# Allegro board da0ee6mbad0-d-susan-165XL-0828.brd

Outline 177.3 x 87.93 mm; copper layers: TOP, IN1, GND1, IN2, SVCC2, SGND2, IN3, GND3, IN4, BOTTOM. Coordinates in mm from the lower left corner of the outline.
Outline path: 0,43.11 0,40.26 0.5,39.76 5.9,39.76 5.9,40.36 arc(6.8,41.26) 7.7,40.36 7.7,39.76 13.1,39.76 13.1,0.5 arc(13.25,0.15) 13.6,0 17.65,0 17.65,4.41 38.95,4.41 38.95,0 43.9,0 arc(44.25,0.15) 44.4,0.5 44.4,12.5 45.4,12.5 arc(46.11,12.79) 46.4,13.5 46.4,32.5 123.1,32.5 arc(123.81,32.79) 124.1,33.5 124.1,54.11 arc(124.25,54.46) 124.6,54.61 128.95,54.61 arc(129.3,54.76) 129.45,55.11 129.45,57.61 129.44,65.41 arc(129.59,65.76) 129.94,65.91 136.1,65.91 136.4,66.21 136.4,66.91 149.8,66.91 149.8,66.21 150.1,65.91 163.31,65.91 163.61,66.21 163.61,67.91 arc(163.7,68.12) 163.91,68.21 164.91,68.21 arc(165.12,68.12) 165.21,67.91 165.21,66.21 165.51,65.91 172.32,65.91 172.32,67.08 arc(173.32,68.08) 174.32,67.08 174.32,65.91 175.3,65.91 arc(175.65,66.06) 175.8,66.41 175.8,82.93 177,82.93 177.3,83.23 177.3,84.13 177,84.43 175.8,84.43 175.8,85.43 177,85.43 177.3,85.73 177.3,86.63 177,86.93 164.62,86.93 164.32,86.63 164.32,85.43 157.52,85.43 157.52,86.63 157.22,86.93 127.83,86.93 127.53,86.63 127.53,85.43 121.73,85.43 121.73,87.33 121.53,87.53 119.93,87.53 119.73,87.33 119.73,86.93 107.77,86.93 107.77,87.33 107.57,87.53 105.97,87.53 105.77,87.33 105.77,86.93 92.28,86.93 91.98,86.63 91.98,85.43 85.18,85.43 85.18,86.63 84.88,86.93 78.8,86.93 78.8,87.63 78.5,87.93 70.9,87.93 70.6,87.63 70.6,86.93 68.7,86.93 68.4,86.63 68.4,86.43 65.8,86.43 65.8,86.63 65.5,86.93 64.05,86.93 63.75,86.63 63.75,85.81 arc(63.3,85.36) 62.85,85.81 62.85,86.63 62.55,86.93 57.43,86.93 57.13,86.63 57.13,85.86 53.1,85.86 53.1,85.16 19.71,85.16 19.71,86.63 19.41,86.93 9.8,86.93 arc(9.09,86.64) 8.8,85.93 8.8,85.31 arc(8.7,85.01) 8.43,84.83 arc(5.17,83.14) 2.86,80.3 arc(1.77,77.95) 0.89,75.53 0.89,75.16 0.78,75.16 arc(0.74,75.03) 0.7,74.9 0.7,70.98 1.2,70.49 1.2,60.49 11.5,60.49 11.5,50.51 1.22,50.51 arc(0.87,50.36) 0.72,50.01 0.72,43.61 0.5,43.61 0,43.11 ; 11.8,78.46 arc(12.09,79.17) 12.8,79.46 14.81,79.46 arc(15,79.38) 15.1,79.2 arc(15.27,78.88) 15.6,78.76 19,78.76 arc(19.33,78.88) 19.5,79.2 arc(19.6,79.38) 19.79,79.46 21.8,79.46 arc(22.51,79.17) 22.8,78.46 22.8,76.26 arc(22.71,76.05) 22.5,75.96 22.3,75.96 arc(21.95,75.81) 21.8,75.46 21.8,74.43 arc(21.85,73.97) 22.01,73.54 22.8,71.96 22.8,67.41 arc(22.51,66.7) 21.8,66.41 12.8,66.41 arc(12.09,66.7) 11.8,67.41 11.8,71.96 12.59,73.54 arc(12.75,73.97) 12.8,74.43 12.8,75.46 arc(12.65,75.81) 12.3,75.96 12.1,75.96 arc(11.89,76.05) 11.8,76.26 11.8,78.46

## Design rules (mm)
constraint set DEFAULT: min track width 0.114
net group DFP-S3(3: nets M_1_DQSN3 M_1_DQSP3
net group DFP-S3(4)W3(2.75)-T23: nets USB_P0_DN USB_P0_DP
net group DFP-S3(3)W4(3.25)-2B: nets M_0_CLKN0 M_0_CLKN2 M_0_CLKP0 M_0_CLKP2 M_1_CLKN0 M_1_CLKN2 M_1_CLKP0 M_1_CLKP2
net group DFP-S3(4)W3(2.75)-23B: nets CAM1_CSI_A_D0N CAM1_CSI_A_D0P CAM1_CSI_A_D1N CAM1_CSI_A_D1P CAM1_CSI_CLKN CAM1_CSI_CLKP CAM2_CSI_CLKN CAM2_CSI_CLKP CAM2_CSI_D0N CAM2_CSI_D0P DDI0_TX0_DN DDI0_TX0_DP DDI0_TX2_DN DDI0_TX2_DP DDI0_TX3_DN DDI0_TX3_DP MCSI_1_CLK_DN MCSI_1_CLK_DP MCSI_1_DATA0_DN MCSI_1_DATA0_DP MCSI_1_DATA1_DN MCSI_1_DATA1_DP MCSI_2_CLK_DN MCSI_2_CLK_DP MCSI_2_DATA_DN MCSI_2_DATA_DP MDSI_A0_DN MDSI_A0_DP MDSI_A1_DN MDSI_A1_DP MDSI_A2_DN MDSI_A2_DP MDSI_A3_DN MDSI_A3_DP MDSI_A_CLKN MDSI_A_CLKP USB_3G_DN USB_3G_DP
net group DFP-S3(4)W3(2.75)-T23B: nets CHG_USBDN CHG_USBDP HDMI_TXCN_R HDMI_TXCP_R HDMI_TXD0N_R HDMI_TXD0P_R HDMI_TXD1N_R HDMI_TXD1P_R HDMI_TXD2N_R HDMI_TXD2P_R N42488414 N42488420 USB2_DEBUG_DN USB2_DEBUG_DP
net group DFP-S4.5W4.5(2.5)-1234B: nets I2C_2MP_CAM_SCL I2C_2MP_CAM_SDA I2C_4_SCL I2C_4_SDA I2C_5_SCL I2C_5_SDA I2C_5MP_CAM_SCL I2C_5MP_CAM_SDA I2C_CODEC_SCL I2C_CODEC_SDA I2C_GYRO_SCL I2C_GYRO_SDA I2C_PMIC_SCL I2C_PMIC_SDA I2C_SENSOR_SCL I2C_SENSOR_SDA I2C_SENSORHUB_SCL I2C_SENSORHUB_SDA
net group DFP-S4.5W4.5(2.5)-T1234B: nets BAT_CLK BAT_DATA GPS_UART_RXD_R GPS_UART_TXD_R I2C_0_SCL I2C_0_SDA UART_BT_CTS UART_BT_RTS UART_BT_RXD UART_BT_TXD UART_GPS_RXD UART_GPS_TXD
net group W4.5(2.5)-2B: nets M_0_CKE0 M_0_CKE1 M_0_CKE2 M_0_CKE3 M_0_ODT0 M_0_ODT2 M_1_CKE0 M_1_CKE1 M_1_CKE2 M_1_CKE3 M_1_ODT0 M_1_ODT2
net group W4.5(2.5)-34B: nets M_0_DM0 M_0_DM1 M_0_DM2 M_0_DM3 M_0_DM4 M_0_DM5 M_0_DM6 M_0_DM7 M_0_DQ0 M_0_DQ1 M_0_DQ2 M_0_DQ3 M_0_DQ4 M_0_DQ5 M_0_DQ6 M_0_DQ7 M_0_DQ8 M_0_DQ9 M_0_DQ10 M_0_DQ11 M_0_DQ12 M_0_DQ13 M_0_DQ14 M_0_DQ15 M_0_DQ16 M_0_DQ17 M_0_DQ18 M_0_DQ19 M_0_DQ20 M_0_DQ21 M_0_DQ22 M_0_DQ23 M_0_DQ24 M_0_DQ25 M_0_DQ26 M_0_DQ27 M_0_DQ28 M_0_DQ29 M_0_DQ30 M_0_DQ31 M_0_DQ32 M_0_DQ33 M_0_DQ34 M_0_DQ35 M_0_DQ36 M_0_DQ37 M_0_DQ38 M_0_DQ39 M_0_DQ40 M_0_DQ41 M_0_DQ42 M_0_DQ43 M_0_DQ44 M_0_DQ45 M_0_DQ46 M_0_DQ47 M_0_DQ48 M_0_DQ49 M_0_DQ50 M_0_DQ51 M_0_DQ52 M_0_DQ53 M_0_DQ54 M_0_DQ55 M_0_DQ56 M_0_DQ57 M_0_DQ58 M_0_DQ59 M_0_DQ60 M_0_DQ61 M_0_DQ62 M_0_DQ63 M_1_DM0 M_1_DM1 M_1_DM2 M_1_DM3 M_1_DM4 M_1_DM5 M_1_DM6 M_1_DM7 M_1_DQ0 M_1_DQ1 M_1_DQ2 M_1_DQ3 M_1_DQ4 M_1_DQ5 M_1_DQ6 M_1_DQ7 M_1_DQ8 M_1_DQ9 M_1_DQ10 M_1_DQ11 M_1_DQ12 M_1_DQ13 M_1_DQ14 M_1_DQ15 M_1_DQ16 M_1_DQ17 M_1_DQ18 M_1_DQ19 M_1_DQ20 M_1_DQ21 M_1_DQ22 M_1_DQ23 M_1_DQ24 M_1_DQ25 M_1_DQ26 M_1_DQ27 M_1_DQ28 M_1_DQ29 M_1_DQ30 M_1_DQ31 M_1_DQ32 M_1_DQ33 M_1_DQ34 M_1_DQ35 M_1_DQ36 M_1_DQ37 M_1_DQ38 M_1_DQ39 M_1_DQ40 M_1_DQ41 M_1_DQ42 M_1_DQ43 M_1_DQ44 M_1_DQ45 M_1_DQ46 M_1_DQ47 M_1_DQ48 M_1_DQ49 M_1_DQ50 M_1_DQ51 M_1_DQ52 M_1_DQ53 M_1_DQ54 M_1_DQ55 M_1_DQ56 M_1_DQ57 M_1_DQ58 M_1_DQ59 M_1_DQ60 M_1_DQ61 M_1_DQ62 M_1_DQ63
net group W4.5(2.5)-1234B: nets ADCDAT BCLK BT_FM_PCM_I2S_CLK_R BT_FM_PCM_I2S_IN_R BT_FM_PCM_I2S_OUT_R BT_FM_PCM_I2S_SYNC_R DACDAT I2S_0_CLK I2S_0_FS I2S_0_RXD I2S_0_TXD I2S_1_CLK I2S_1_FS I2S_1_RXD I2S_1_TXD I2S_2_CLK I2S_2_FS I2S_2_RXD I2S_2_TXD LRCK PLT_CLK0_CAM1 PLT_CLK1_CAM2 SOC_SPI_CLK SOC_SPI_CS# SOC_SPI_MISO SOC_SPI_MOSI SUS_CLK_GPS SUS_CLK_WLAN
net group W4.5(2.5)-T123B: nets SIM_CLK SIM_DATA SIM_RST SOC_XTAL_IN SOC_XTAL_OUT STM_12M_IN STM_12M_OUT STM_12M_OUT_R USIM_DETECT
net group W4.5(2.5)-T1234: nets EMMC_CLK EMMC_CMD EMMC_DATA_0 EMMC_DATA_1 EMMC_DATA_2 EMMC_DATA_3 EMMC_DATA_4 EMMC_DATA_5 EMMC_DATA_6 EMMC_DATA_7 EMMC_RESET SDIO2_CLK SDIO2_CMD SDIO2_DATA0 SDIO2_DATA1 SDIO2_DATA2 SDIO2_DATA3 SDIO3_CD# SDIO3_CLK SDIO3_CMD SDIO3_DATA_0 SDIO3_DATA_1 SDIO3_DATA_2 SDIO3_DATA_3
net group W4.5(2.5)-T1234B: nets BT_DEV_EN CAMERA_1_RESET# CAMERA_2_RESET# CLK_USB_REF_DN CLK_USB_REF_DP CODEC_RESET# CORE_PWROK DEBUG_SVID_ALERT_B DEBUG_SVID_CLK DEBUG_SVID_DATA EMMC_RCOMP LPC_AD0 LPC_AD1 LPC_AD2 LPC_AD3 LPC_CLKOUT_1 LPC_FRAME# PLTRST# PROCHOT# RSMRST# RTC_XTAL_IN RTC_XTAL_OUT S_D_RS SENSOR_HUB_RST# SENSOR_HUB_RST_3P3_R SLP_S0IX# SLP_S3# SLP_S3#_EN SLP_S4# SOC_PWRBTN# SOC_RTEST# SOC_RTEST#_R SRT_CRST# SUS_PWRDNACK SUS_PWRDOWNACK SVID_ALERT# SVID_ALERT#_R SVID_CLK SVID_CLK_R SVID_DATA SVID_DATA_R TOUCH_RESET# USB_RCOMP
net group W4.5-T1234B: nets DDI0_RCOMP_DN DDI0_RCOMP_DP GPIO_RCOMP18 HDA_RCOMP ICLK_ICOMP ICLK_RCOMP LPC_RCOMP MCSI_COMP MDSI_COMP SDIO3_RCOMP USB_HSIC_RCOMP
net group W5-T1234B: nets DDR3_RCOMP0 DDR3_RCOMP1 DDR3_RCOMP2
net group W6(3.5: nets M_0_CA0 M_0_CA1 M_0_CA2 M_0_CA3 M_0_CA4 M_0_CA5 M_0_CA6 M_0_CA7 M_0_CA8 M_0_CA9 M_0_CS0# M_0_CS2# M_1_CA0 M_1_CA1 M_1_CA2 M_1_CA3 M_1_CA4 M_1_CA5 M_1_CA6 M_1_CA7 M_1_CA8 M_1_CA9 M_1_CS0# M_1_CS2#
net group W10-T1234B: nets +1V05 +1V8 +1V8S5 +1V24 +1V24S5 +1V24SX +1VS5 +2V8_CAM +2V85 +3.3V_PA +3V3 +3V3_NGFF +3V3PCU +3V3S5 +5V +V_VCC +V_VNN +VBL_LCM +VDDQ +VDDQ_VTT +VHDMI +VSDIO CBUCK_OUT VIN_LDO WLBT_3V3
net group W11.5-B: nets ANT_0 ANT_1 DB_ANT_B DB_ANT_C GPS_ANT GPS_EXT_LN_OUT GPS_EXT_LNA_IN GPS_RFIP GPS_SAW1_IN GPS_SAW1_OUT GPS_SAW1_OUT1 GPS_SAW2_OUT
net group W15-T3: nets HP_L1 HP_OUT_L HP_OUT_R HP_R1
net group W20-T1234B: nets CPU_VREF
net group W30-T2: nets SPK_LN SPK_LP SPK_RN SPK_RP

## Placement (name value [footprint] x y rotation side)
C1  4.7u/6.3V_4  [CC0402_S]  2.56 48.16 180 top
C2  0.1U/10V_4  [CC0402_S]  2.56 47.27 180 top
C3  0.1u/25V_4  [CC0402_S]  5.86 48.92 180 top
C4  0.1U/10V_4  [CC0402_S]  34.06 39.02 0 top
C5  1u/6.3V_4  [CC0402_S]  34.06 38.13 180 top
C6  *10P/50V_2  [CC0201_S]  34.57 37.11 180 top
C7  1u/6.3V_4  [CC0402_S]  35.71 38.51 90 top
C8  0.1U/10V_4  [CC0402_S]  36.47 34.82 90 top
C9  0.1U/10V_4  [CC0402_S]  36.6 38.51 270 top
C10  0.1U/10V_4  [CC0402_S]  37.49 38.51 270 top
C11  0.47U/6.3V_4  [CC0402_S]  39.27 76.73 90 top
C12  0.47U/6.3V_4  [CC0402_S]  39.27 74.19 270 top
C13  0.47U/6.3V_4  [CC0402_S]  39.27 69.37 90 top
C14  0.47U/6.3V_4  [CC0402_S]  39.27 59.21 90 top
C15  0.47U/6.3V_4  [CC0402_S]  39.27 55.27 90 top
C16  0.47U/6.3V_4  [CC0402_S]  39.27 52.6 270 top
C17  0.47U/6.3V_4  [CC0402_S]  41.93 74.19 90 top
C18  0.47U/6.3V_4  [CC0402_S]  41.93 55.27 270 top
C19  0.1u/10V_2  [CC0201_S]  42.44 63.53 270 top
C20  0.47uF/6.3V_2  [CC0201_S]  46.5 66.07 0 top
C21  0.47uF/6.3V_2  [CC0201_S]  48.66 63.88 270 top
C22  0.47uF/6.3V_2  [CC0201_S]  47.77 60.86 180 top
C23  0.47uF/6.3V_2  [CC0201_S]  47.85 68.73 270 top
C24  *0.1u/10V_2  [CC0201_S]  47.85 66.3 90 top
C25  *0.1u/10V_4  [CC0402_S]  48.28 75.34 90 top
C26  0.47uF/6.3V_2  [CC0201_S]  48.54 68.73 270 top
C27  0.47uF/6.3V_2  [CC0201_S]  49.25 66.68 90 top
C28  0.47uF/6.3V_2  [CC0201_S]  49.3 69.37 270 top
C29  0.47uF/6.3V_2  [CC0201_S]  49.3 61.62 90 top
C30  0.47uF/6.3V_2  [CC0201_S]  49.3 63.88 90 top
C31  0.47uF/6.3V_2  [CC0201_S]  49.98 59.51 90 top
C32  0.47uF/6.3V_2  [CC0201_S]  50.06 69.37 270 top
C33  0.47uF/6.3V_2  [CC0201_S]  50.06 61.62 90 top
C34  1U/10V_2  [CC0201_S]  51.15 68.61 180 top
C35  0.47uF/6.3V_2  [CC0201_S]  51.15 59.97 270 top
C36  0.47uF/6.3V_2  [CC0201_S]  51.36 62.97 90 top
C37  *1U/10V_2  [CC0201_S]  51.38 65.79 270 top
C38  0.47uF/6.3V_2  [CC0201_S]  51.38 64.37 90 top
C39  1U/10V_2  [CC0201_S]  51.58 67.34 0 top
C40  0.47uF/6.3V_2  [CC0201_S]  51.58 66.7 180 top
C41  3300p/50V_4  [CC0402_S]  51.2 38.13 90 top
C42  *.1U/25V/X7R_6  [CC0603]  51.84 55.53 0 top
C43  0.47uF/6.3V_2  [CC0201_S]  52.09 68.35 90 top
C44  0.47uF/6.3V_2  [CC0201_S]  52.42 65.15 270 top
C45  3300p/50V_4  [CC0402_S]  52.09 38.13 90 top
C46  *1U/10V_2  [CC0201_S]  52.6 61.49 180 top
C47  0.47uF/6.3V_2  [CC0201_S]  53.36 68.35 90 top
C48  0.1U/10V_4  [CC0402_S]  52.98 38.13 270 top
C49  0.47uF/6.3V_2  [CC0201_S]  53.79 67.36 180 top
C50  1U/10V_2  [CC0201_S]  53.87 70.13 90 top
C51  0.47uF/6.3V_2  [CC0201_S]  53.9 65.69 180 top
C52  0.47uF/6.3V_2  [CC0201_S]  54 64.54 180 top
C53  0.47uF/6.3V_2  [CC0201_S]  54 63.65 0 top
C54  0.47uF/6.3V_2  [CC0201_S]  54 62.38 180 top
C55  1u/10V_4  [CC0402_S]  53.87 38.13 90 top
C56  0.47uF/6.3V_2  [CC0201_S]  54.76 71.15 180 top
C57  0.47uF/6.3V_2  [CC0201_S]  54.76 70.38 180 top
C58  0.47uF/6.3V_2  [CC0201_S]  54.76 69.62 180 top
C59  0.47uF/6.3V_2  [CC0201_S]  54.94 67.92 90 top
C60  0.47uF/6.3V_2  [CC0201_S]  55.14 64.54 180 top
C61  0.47uF/6.3V_2  [CC0201_S]  55.14 61.88 90 top
C62  0.47uF/6.3V_2  [CC0201_S]  55.39 60.73 0 top
C64  0.47uF/6.3V_2  [CC0201_S]  55.7 67.92 90 top
C65  1U/10V_2  [CC0201_S]  55.72 69.24 90 top
C66  0.47uF/6.3V_2  [CC0201_S]  55.9 62.38 270 top
C67  0.47uF/6.3V_2  [CC0201_S]  56.03 66.19 180 top
C68  0.47uF/6.3V_2  [CC0201_S]  56.41 63.78 270 top
C69  *.1U/25V/X7R_6  [CC0603]  57.17 58.83 0 top
C70  *10P/50V_2  [CC0201_S]  57.68 72.26 180 top
C71  4.7U/6.3V_6  [CC0603]  57.93 62 0 top
C72  0.47uF/6.3V_2  [CC0201_S]  59.46 60.86 180 top
C73  0.47uF/6.3V_2  [CC0201_S]  59.46 60.22 180 top
C74  0.47uF/6.3V_2  [CC0201_S]  59.46 59.59 180 top
C75  *.1U/25V/X7R_6  [CC0603]  60.73 69.11 0 top
C76  *.1U/25V/X7R_6  [CC0603]  60.88 63.88 270 top
C77  *0.1u/10V_4  [CC0402_S]  64.03 46.64 270 top
C78  *1u/6.3V_4  [CC0402_S]  65.68 47.78 0 top
C79  0.1u/10V_4  [CC0402_S]  65.81 81.43 0 top
C80  *0.1u/10V_4  [CC0402_S]  67.46 47.78 180 top
C81  1u/6.3V_4  [CC0402_S]  68.98 81.69 180 top
C82  *10P/50V_2  [CC0201_S]  19 28.35 270 bottom
C83  0.1u/10V_2  [CC0201_S]  71.02 74.45 90 top
C84  0.1u/10V_2  [CC0201_S]  71.78 74.45 90 top
C85  0.1u/10V_2  [CC0201_S]  72.54 74.45 90 top
C86  0.1u/10V_2  [CC0201_S]  73.3 74.45 90 top
C87  *0.1u/10V_2  [CC0201_S]  73.56 55.91 0 top
C88  *10P/50V_2  [CC0201_S]  74.7 65.05 90 top
C89  0.1u/10V_2  [CC0201_S]  75.08 74.45 90 top
C90  0.1u/10V_2  [CC0201_S]  75.84 74.45 90 top
C91  0.1u/10V_2  [CC0201_S]  76.6 74.45 90 top
C92  *0.1u/10V_4  [CC0402_S]  77.16 68.23 180 top
C93  0.1u/10V_2  [CC0201_S]  77.37 74.45 90 top
C94  4.7u/6.3V_4  [CC0402_S]  80.54 78.26 270 top
C95  0.1u/10V_4  [CC0402_S]  82.37 70.51 270 top
C96  0.1u/10V_4  [CC0402_S]  83.69 70 180 top
C97  0.1u/10V_4  [CC0402_S]  85.16 69.09 270 top
C98  0.1U/25V_4  [CC0402_S]  91.21 35.84 90 top
C99  0.1U/25V_4  [CC0402_S]  91.59 46.43 270 top
C100  0.1U/25V_4  [CC0402_S]  97.56 35.84 90 top
C101  0.1U/25V_4  [CC0402_S]  98.45 35.84 90 top
C102  0.1u/10V_4  [CC0402_S]  98.57 73.43 0 top
C103  0.1U/25V_4  [CC0402_S]  99.34 42.57 270 top
C104  18P/25V/COG_2  [CC0201_S]  99.34 37.87 90 top
C105  1u/6.3V_4  [CC0402_S]  99.34 35.84 270 top
C106  0.1U/25V_4  [CC0402_S]  100.23 42.57 90 top
C107  18P/25V/COG_2  [CC0201_S]  99.34 39.02 90 top
C108  0.1u/10V_4_X7R  [CC0402_S]  103.65 77.75 270 top
C109  NG@1u/6.3V_4  [CC0402_S]  110.51 69.24 90 top
C110  4.7u/6.3V_6  [CC0603]  110.89 62 180 top
C111  *10P/50V_2  [CC0201_S]  111.02 56.03 0 top
C112  0.1u/10V_4  [CC0402_S]  111.27 60.86 180 top
C113  39p/50V_4  [CC0402_S]  111.27 59.97 180 top
C114  NG@0.1U/25_4  [CC0402_S]  111.4 69.24 90 top
C115  1U/6.3V_4  [CC0402_S]  113.31 64.42 90 top
C116  NG@33P/50V_4  [CC0402_S]  114.07 69.24 90 top
C117  *10P/50V_2  [CC0201_S]  114.83 55.65 90 top
C118  *0.1u/16V_4  [CC0402_S]  115.59 55.4 270 top
C119  0.1u/10V_4  [CC0402_S]  115.97 64.42 90 top
C120  0.1u/10V_4  [CC0402_S]  116.48 55.4 270 top
C121  0.1u/10V_4  [CC0402_S]  120.55 60.61 0 top
C122  0.1u/10V_4  [CC0402_S]  120.55 57.43 0 top
C123  4.7u/6.3V_6  [CC0603]  120.9 59.46 0 top
C124  10u/6.3V_6  [CC0603]  120.9 56.26 180 top
C125  0.1U/10V_4  [CC0402_S]  124.99 65.56 270 top
C126  0.1U/10V_4  [CC0402_S]  134.13 70.51 90 top
C127  4.7u/6.3V_4  [CC0402_S]  135.02 70.51 270 top
C128  *10P/50V_2  [CC0201_S]  135.79 70.77 90 top
C129  *1u/10V_4  [CC0402_S]  157.12 77.47 90 top
C130  *0.1u/25V_4  [CC0402_S]  158.77 77.47 90 top
C131  *0.1u/25V_4  [CC0402_S]  164.36 78.11 90 top
C132  4.7u/6.3V_4  [CC0402_S]  161.57 78.61 90 top
C133  0.1u/25V_4  [CC0402_S]  150.9 78.61 270 top
C134  0.1u/25V_4  [CC0402_S]  150.77 84.48 90 top
C135  0.1U/10V_4  [CC0402_S]  2.13 44.48 270 bottom
C136  4.7u/6.3V_4  [CC0402_S]  2.99 44.22 270 bottom
C137  22p/50V_4  [CC0402_S]  13.99 44.35 0 bottom
C138  NG@100pf/10V_4  [CC0402_S]  15.01 14.38 180 bottom
C139  NG@1u/6.3V_4  [CC0402_S]  15.01 15.27 0 bottom
C140  *1pf/10V_4  [CC0402_S]  14.88 6.76 180 bottom
C141  NG@100pf/10V_4  [CC0402_S]  20.34 35.08 180 bottom
C142  *1pf/10V_4  [CC0402_S]  15.52 39.02 180 bottom
C143  NG@0.1u/25V_4  [CC0402_S]  20.34 34.19 0 bottom
C144  NG@1u/6.3V_4  [CC0402_S]  20.34 33.3 0 bottom
C145  NG@1u/6.3V_4  [CC0402_S]  20.34 36.86 0 bottom
C146  NG@100pf/10V_4  [CC0402_S]  20.34 35.97 180 bottom
C147  1u/10V_4  [CC0402_S]  18.82 82.58 0 bottom
C148  NG@0.1u/25V_4  [CC0402_S]  16.79 15.27 0 bottom
C149  NG@1u/6.3V_4  [CC0402_S]  16.79 16.16 0 bottom
C150  NG@100pf/10V_4  [CC0402_S]  16.79 14.38 180 bottom
C151  *22p/50V_4  [CC0402_S]  18.31 57.94 90 bottom
C152  0.1U/10V_4  [CC0402_S]  20.6 81.43 180 bottom
C153  NG@33P/50V_4  [CC0402_S]  20.98 11.84 180 bottom
C154  NG@22p/50V_4  [CC0402_S]  20.98 10.95 180 bottom
C155  NG@0.1u/25V_4  [CC0402_S]  20.98 10.06 180 bottom
C156  NG@100uF/6.3V_1206  [CC1206]  21.49 16.41 0 bottom
C157  NG@100uF/6.3V_1206  [CC1206]  21.49 13.87 0 bottom
C158  NG@100uF/6.3V_1206  [CC1206]  42.19 9.55 270 bottom
C159  10u/6.3V_4  [CC0402_S]  21.49 58.32 180 bottom
C160  0.1U/10V_4  [CC0402_S]  21.87 61.37 270 bottom
C161  0.1U/10V_4  [CC0402_S]  20.6 57.43 0 bottom
C162  1u/10V_4  [CC0402_S]  20.6 56.54 0 bottom
C163  NG@33P/50V_4  [CC0402_S]  24.79 10.44 90 bottom
C164  0.1u/10V_4  [CC0402_S]  25.3 77.88 90 bottom
C165  0.1u/10V_4  [CC0402_S]  25.3 75.08 90 bottom
C166  0.47U/6.3V_4  [CC0402_S]  25.42 53.11 270 bottom
C167  0.1u/10V_4  [CC0402_S]  25.42 51.33 90 bottom
C168  0.47U/6.3V_4  [CC0402_S]  26.06 80.67 90 bottom
C169  *0.1u/10V_4  [CC0402_S]  26.18 48.85 270 bottom
C170  0.47U/6.3V_4  [CC0402_S]  26.69 75.59 0 bottom
C171  0.47U/6.3V_4  [CC0402_S]  26.69 74.7 0 bottom
C172  0.47U/6.3V_4  [CC0402_S]  26.57 69.37 0 bottom
C173  0.1u/10V_4  [CC0402_S]  26.57 68.48 0 bottom
C174  0.47U/6.3V_4  [CC0402_S]  26.57 67.59 0 bottom
C175  0.47U/6.3V_4  [CC0402_S]  26.69 61.75 0 bottom
C176  0.1u/10V_4  [CC0402_S]  26.69 60.86 0 bottom
C177  0.47U/6.3V_4  [CC0402_S]  26.69 59.97 0 bottom
C178  0.47U/6.3V_4  [CC0402_S]  26.69 54.64 0 bottom
C179  0.47U/6.3V_4  [CC0402_S]  26.69 53.75 0 bottom
C180  0.47U/6.3V_4  [CC0402_S]  27.07 72.54 270 bottom
C181  0.47U/6.3V_4  [CC0402_S]  27.07 70.77 270 bottom
C182  0.47U/6.3V_4  [CC0402_S]  27.07 58.57 90 bottom
C183  0.47U/6.3V_4  [CC0402_S]  27.07 56.8 90 bottom
C184  GS@0.1U/10V_4  [CC0402_S]  28.47 20.22 0 bottom
C185  GS@2.2uF/6.3V_4  [CC0402_S]  28.47 19.33 180 bottom
C186  GS@0.1U/10V_4  [CC0402_S]  28.47 18.44 180 bottom
C187  NG@33P/50V_4  [CC0402_S]  29.23 10.44 90 bottom
C188  0.1U/10V_4  [CC0402_S]  29.11 29.74 0 bottom
C189  *0.1u/10V_4  [CC0402_S]  29.61 80.67 90 bottom
C190  0.1u/10V_4  [CC0402_S]  29.74 48.85 270 bottom
C191  GS@0.01uF/25V_4  [CC0402_S]  29.99 24.28 90 bottom
C192  GS@0.1U/10V_4  [CC0402_S]  29.87 15.65 270 bottom
C193  0.47U/6.3V_4  [CC0402_S]  29.99 65.94 90 bottom
C194  0.47U/6.3V_4  [CC0402_S]  29.99 63.53 270 bottom
C195  NG@33P/50V_4  [CC0402_S]  30.12 10.44 90 bottom
C196  0.1U/10V_4  [CC0402_S]  33.5 30.18 90 top
C197  GS@1u/10V_4  [CC0402_S]  30.88 24.28 270 bottom
C198  GS@2.2uF/6.3V_4  [CC0402_S]  30.76 15.65 270 bottom
C199  NG@33P/50V_4  [CC0402_S]  31.01 10.44 90 bottom
C200  1u/6.3V_4  [CC0402_S]  32.61 30.18 270 top
C201  0.1u/10V_4  [CC0402_S]  31.65 65.94 90 bottom
C202  0.1u/10V_4  [CC0402_S]  31.65 63.53 270 bottom
C203  GS@1u/10V_4  [CC0402_S]  31.77 24.28 270 bottom
C204  1u/6.3V_4  [CC0402_S]  31.01 29.74 0 bottom
C205  GS@1u/6.3V_4  [CC0402_S]  32.66 24.28 90 bottom
C206  0.47U/6.3V_4  [CC0402_S]  33.3 65.94 90 bottom
C207  0.47U/6.3V_4  [CC0402_S]  33.3 63.53 270 bottom
C209  GS@1u/6.3V_4  [CC0402_S]  33.93 22.51 90 bottom
C210  0.47U/6.3V_4  [CC0402_S]  34.19 48.92 90 bottom
C211  GS@0.1U/10V_4  [CC0402_S]  34.95 24.66 180 bottom
C212  0.47U/6.3V_4  [CC0402_S]  34.95 65.94 90 bottom
C213  0.47U/6.3V_4  [CC0402_S]  34.95 63.53 270 bottom
C214  GS@1u/10V_4  [CC0402_S]  35.33 20.85 180 bottom
C215  GS@47pF/50V_4  [CC0402_S]  35.33 19.97 0 bottom
C216  0.47U/6.3V_4  [CC0402_S]  35.84 80.67 270 bottom
C217  0.47U/6.3V_4  [CC0402_S]  36.6 65.94 90 bottom
C218  0.47U/6.3V_4  [CC0402_S]  36.6 63.53 270 bottom
C219  0.47U/6.3V_4  [CC0402_S]  36.73 80.67 270 bottom
C220  0.47U/6.3V_4  [CC0402_S]  36.85 48.92 90 bottom
C221  NG@2200p/50V_4  [CC0402_S]  42.44 4.98 0 bottom
C222  0.1u/10V_4  [CC0402_S]  37.61 80.67 270 bottom
C223  GS@39nF/16V_4  [CC0402_S]  37.61 15.65 270 bottom
C224  0.1u/10V_4  [CC0402_S]  37.74 48.92 90 bottom
C225  0.1U/10V_4  [CC0402_S]  38.38 29.74 180 bottom
C226  NG@0.01uF/25V_4  [CC0402_S]  42.44 6 0 bottom
C227  0.47U/6.3V_4  [CC0402_S]  38.12 65.94 90 bottom
C228  0.47U/6.3V_4  [CC0402_S]  38.12 63.53 270 bottom
C229  GS@470pF/50V_4  [CC0402_S]  38.46 23.65 270 bottom
C230  0.47U/6.3V_4  [CC0402_S]  38.5 80.67 270 bottom
C231  GS@33nF/25V_4  [CC0402_S]  38.5 15.65 270 bottom
C232  0.47U/6.3V_4  [CC0402_S]  38.63 48.92 90 bottom
C234  0.1u/10V_4  [CC0402_S]  40.92 59.84 270 bottom
C235  0.47U/6.3V_4  [CC0402_S]  40.76 57.94 270 bottom
C236  *0.47U/6.3V_4  [CC0402_S]  40.66 56.03 270 bottom
C237  0.1u/10V_4  [CC0402_S]  40.66 54.13 270 bottom
C238  0.47U/6.3V_4  [CC0402_S]  40.92 52.22 270 bottom
C239  0.47U/6.3V_4  [CC0402_S]  41.55 79.27 180 bottom
C240  0.1u/10V_4  [CC0402_S]  41.55 78.26 180 bottom
C241  *0.47U/6.3V_4  [CC0402_S]  41.55 77.24 180 bottom
C242  0.1u/10V_4  [CC0402_S]  41.55 76.23 180 bottom
C243  0.47U/6.3V_4  [CC0402_S]  41.55 75.21 180 bottom
C244  0.47uF/6.3V_2  [CC0201_S]  41.68 66.57 0 bottom
C245  0.47uF/6.3V_2  [CC0201_S]  41.68 65.81 0 bottom
C246  0.47uF/6.3V_2  [CC0201_S]  41.68 63.02 0 bottom
C247  0.47uF/6.3V_2  [CC0201_S]  41.68 61.24 0 bottom
C248  0.47uF/6.3V_2  [CC0201_S]  41.81 70 270 bottom
C249  0.47uF/6.3V_2  [CC0201_S]  41.81 68.86 270 bottom
C250  0.47uF/6.3V_2  [CC0201_S]  41.81 60.22 270 bottom
C251  0.47uF/6.3V_2  [CC0201_S]  41.81 58.29 90 bottom
C252  *2.7pF/50V_4  [CC0402_S]  44.22 24.16 270 bottom
C253  GS@47pF/50V_4  [CC0402_S]  44.22 22.38 90 bottom
C254  *2.7pF/50V_4  [CC0402_S]  44.57 20.98 180 bottom
C255  0.47uF/6.3V_2  [CC0201_S]  47.77 73.94 0 bottom
C256  0.47uF/6.3V_2  [CC0201_S]  48.03 54.38 0 bottom
C257  0.47uF/6.3V_2  [CC0201_S]  48.03 53.75 0 bottom
C258  0.47uF/6.3V_2  [CC0201_S]  48.92 73.94 180 bottom
C259  0.47uF/6.3V_2  [CC0201_S]  48.92 54.13 90 bottom
C260  0.47uF/6.3V_2  [CC0201_S]  49.81 54.38 0 bottom
C261  0.47uF/6.3V_2  [CC0201_S]  50.06 73.94 0 bottom
C262  0.47uF/6.3V_2  [CC0201_S]  50.95 54.38 0 bottom
C263  0.47uF/6.3V_2  [CC0201_S]  51.2 73.94 180 bottom
C264  *.1U/25V/X7R_6  [CC0603]  51.46 52.86 180 bottom
C265  0.47uF/6.3V_2  [CC0201_S]  52.09 54.38 0 bottom
C266  0.47uF/6.3V_2  [CC0201_S]  53.11 74.19 270 bottom
C267  0.47uF/6.3V_2  [CC0201_S]  53.24 54.38 0 bottom
C268  0.47uF/6.3V_2  [CC0201_S]  53.87 74.19 270 bottom
C269  0.47uF/6.3V_2  [CC0201_S]  54.38 54.38 180 bottom
C270  0.47uF/6.3V_2  [CC0201_S]  54.76 74.19 270 bottom
C271  0.47uF/6.3V_2  [CC0201_S]  55.52 54.38 180 bottom
C272  0.47uF/6.3V_2  [CC0201_S]  56.03 73.94 0 bottom
C273  0.47uF/6.3V_2  [CC0201_S]  57.17 73.94 0 bottom
C274  0.1u/10V_2  [CC0201_S]  59.08 75.08 180 bottom
C275  18P/25V/COG_2  [CC0201_S]  59.08 75.72 180 bottom
C276  0.1u/10V_2  [CC0201_S]  59.46 34.95 180 bottom
C277  0.47uF/6.3V_2  [CC0201_S]  61.49 64.16 90 bottom
C278  0.47uF/6.3V_2  [CC0201_S]  61.49 63.02 90 bottom
C279  0.47uF/6.3V_2  [CC0201_S]  61.49 61.11 90 bottom
C280  0.47uF/6.3V_2  [CC0201_S]  61.49 59.97 90 bottom
C281  0.47uF/6.3V_2  [CC0201_S]  61.49 58.83 90 bottom
C282  0.47uF/6.3V_2  [CC0201_S]  61.74 70.21 180 bottom
C283  0.47uF/6.3V_2  [CC0201_S]  61.74 68.86 180 bottom
C284  0.47uF/6.3V_2  [CC0201_S]  61.74 68.1 180 bottom
C285  0.47uF/6.3V_2  [CC0201_S]  61.74 67.21 180 bottom
C286  0.47uF/6.3V_2  [CC0201_S]  61.74 66.45 180 bottom
C287  0.47uF/6.3V_2  [CC0201_S]  61.74 65.05 180 bottom
C288  18P/25V/COG_2  [CC0201_S]  61.87 75.72 0 bottom
C289  0.47uF/6.3V_2  [CC0201_S]  62.25 58.83 90 bottom
C290  1U/10V_2  [CC0201_S]  62.51 74.45 90 bottom
C291  1U/10V_2  [CC0201_S]  62.89 75.59 270 bottom
C292  0.47uF/6.3V_2  [CC0201_S]  63.14 69.75 180 bottom
C293  15P/25V_2  [CC0201_S]  64.03 63.02 270 bottom
C294  15P/25V_2  [CC0201_S]  64.03 61.62 90 bottom
C295  10u/6.3V_4  [CC0402_S]  65.17 73.43 270 bottom
C296  10u/6.3V_4  [CC0402_S]  65.81 66.83 90 bottom
C297  1U/6.3V_4  [CC0402_S]  81.81 44.98 90 bottom
C298  0.1U/25V_4  [CC0402_S]  93.49 48.03 90 bottom
C299  0.1U/25V_4  [CC0402_S]  93.75 40.54 90 bottom
C300  10u/6.3V_6  [CC0603]  94.38 38.25 90 bottom
C301  0.1U/25V_4  [CC0402_S]  95.53 38.63 90 bottom
C302  0.01u/50V_4  [CC0402_S]  95.53 36.86 270 bottom
C303  0.1U/25V_4  [CC0402_S]  98.19 42.19 90 bottom
C304  *10P/50V_2  [CC0201_S]  111.4 70 90 bottom
C305  22p/50V_4  [CC0402_S]  111.02 68.35 90 bottom
C306  4.7u/6.3V_4  [CC0402_S]  110.89 71.81 90 bottom
C307  *10P/50V_2  [CC0201_S]  110.26 65.05 90 bottom
C308  10u/6.3V_6  [CC0603]  112.04 77.62 0 bottom
C309  10u/6.3V_6  [CC0603]  112.04 76.35 0 bottom
C310  22p/50V_4  [CC0402_S]  110.51 66.96 0 bottom
C311  2.2U/6.3V_4  [CC0402_S]  111.4 73.56 90 bottom
C312  0.1U/10V_4  [CC0402_S]  111.78 71.81 270 bottom
C313  *10P/50V_2  [CC0201_S]  111.15 65.05 270 bottom
C314  1000p/50V_4  [CC0402]  111.91 75.08 0 bottom
C315  22p/50V_4  [CC0402_S]  111.91 67.11 90 bottom
C316  0.1U/10V_4  [CC0402_S]  112.29 73.56 270 bottom
C317  22p/50V_4  [CC0402_S]  112.8 67.11 90 bottom
C318  *10P/50V_2  [CC0201_S]  116.99 80.68 0 bottom
C319  0.1U/25V_4  [CC0402_S]  115.59 60.89 90 bottom
C320  22p/50V_4  [CC0402_S]  113.69 67.11 90 bottom
C321  0.1U/10V_4  [CC0402_S]  115.52 79.53 180 bottom
C322  2.2U/6.3V_4  [CC0402_S]  115.08 78.64 0 bottom
C323  22p/50V_4  [CC0402_S]  114.58 67.08 90 bottom
C324  0.1U/25V_4  [CC0402_S]  116.99 56.92 180 bottom
C325  22p/50V_4  [CC0402_S]  115.47 67.08 90 bottom
C326  100pf/10V_4  [CC0402_S]  117.24 81.94 90 bottom
C327  4.7u/6.3V_4  [CC0402_S]  116.81 79.4 90 bottom
C328  22p/50V_4  [CC0402_S]  116.35 67.08 90 bottom
C329  1u/10V_4  [CC0402_S]  117.37 77.62 270 bottom
C330  0.1u/10V_4  [CC0402_S]  119.15 60.89 270 bottom
C331  22p/50V_4  [CC0402_S]  117.24 67.08 90 bottom
C332  0.1U/10V_4  [CC0402_S]  118.64 77.88 0 bottom
C333  10u/6.3V_6  [CC0603]  119.78 79.15 180 bottom
C334  *0.1U/10V_4  [CC0402_S]  118.13 67.84 90 bottom
C335  4.7u/6.3V_4  [CC0402_S]  119.91 77.62 90 bottom
C336  *33P/50V_4  [CC0402_S]  119.02 65.36 90 bottom
C337  *10P/50V_2  [CC0201_S]  119.15 66.57 180 bottom
C338  4.7u/6.3V_4  [CC0402_S]  120.8 77.62 90 bottom
C339  *0.1U/10V_4  [CC0402_S]  119.91 67.84 90 bottom
C340  0.1U/10V_4  [CC0402_S]  123.34 74.58 180 top
C341  2.2U/6.3V_4  [CC0402_S]  123.34 73.69 180 top
C342  2.2U/6.3V_4  [CC0402_S]  123.34 72.8 0 top
C343  0.1U/10V_4  [CC0402_S]  123.34 71.91 180 top
C344  2.2U/6.3V_4  [CC0402_S]  123.34 71.02 0 top
C345  2.2U/6.3V_4  [CC0402_S]  123.34 70.13 0 top
C346  *33P/50V_4  [CC0402_S]  120.8 65.36 90 bottom
C347  10u/6.3V_6  [CC0603]  123.47 77.37 0 top
C348  10u/6.3V_6  [CC0603]  123.47 75.85 180 top
C349  *10P/50V_2  [CC0201_S]  120.67 66.57 0 bottom
C350  680p/50V_4  [CC0402_S]  127.99 75.9 270 bottom
C351  680p/50V_4  [CC0402_S]  129.77 75.9 270 bottom
C352  680p/50V_4  [CC0402_S]  130.65 75.9 270 bottom
C353  680p/50V_4  [CC0402_S]  132.43 75.9 270 bottom
C354  4.7u/6.3V_4  [CC0402_S]  136.04 76.35 90 bottom
C355  100pf/10V_4  [CC0402_S]  137.44 76.86 0 bottom
C356  10u/6.3V_6  [CC0603]  171.6 74.7 180 bottom
C357  0.1U/25V_4  [CC0402_S]  167.66 74.45 270 bottom
C358  0.1U/25V_4  [CC0402_S]  171.22 73.43 180 bottom
C359  0.22u/10V_4  [CC0402_S]  173.76 74.7 270 bottom
C360  4.7u/10V_6  [CC0603]  165.76 81.94 90 bottom
C361  10U/6.3V_4  [CC0402_S]  154.33 81.79 0 top
C362  0.1u/25V_4  [CC0402_S]  154.33 82.81 180 top
C363  0.1u/25V_4  [CC0402_S]  148.61 82.04 180 bottom
C364  10U/6.3V_4  [CC0402_S]  148.61 82.93 0 bottom
C365  1u/10V_4  [CC0402_S]  160.17 77.6 0 top
C366  68P/50V_4  [CC0402_S]  160.17 76.71 0 top
C367  2.7pF/50V_4  [CC0402_S]  162.46 78.61 270 top
C368  *10P/50V_2  [CC0201_S]  151.15 77.98 0 bottom
C369  68P/50V_4  [CC0402_S]  154.33 79 180 top
C370  *10P/50V_2  [CC0201_S]  160.42 79.25 0 top
C371  0.1U/10V_4  [CC0402_S]  154.33 78.11 0 top
C372  4.7u/6.3V_4  [CC0402_S]  149.5 78.49 270 bottom
C373  10P/50V/C0G_4  [CC0402_S]  167.57 71.82 180 bottom
C374  10P/50V/C0G_4  [CC0402_S]  152.42 67.51 180 bottom
C375  0.1U/25V_4  [CC0402_S]  111.4 44.22 0 top
C376  0.1U/25V_4  [CC0402_S]  111.66 51.97 270 top
C377  *1.6p/50V_4  [CC0402]  70.63 77.24 270 top
C378  *1.6p/50V_4  [CC0402]  71.65 77.24 270 top
C437  *1.6p/50V_4  [CC0402]  72.67 77.24 270 top
C447  *1.6p/50V_4  [CC0402]  73.68 77.24 270 top
C452  *1.6p/50V_4  [CC0402]  74.7 77.24 270 top
C458  *1.6p/50V_4  [CC0402]  75.71 77.24 270 top
C466  *1.6p/50V_4  [CC0402]  76.73 77.24 270 top
C756  *1.6p/50V_4  [CC0402]  77.75 77.24 270 top
C757  0.1U/25V_4  [CC0402_S]  46.12 54.33 180 bottom
C758  0.1U/25V_4  [CC0402_S]  46.96 53.09 270 bottom
CN1  *AXE160224D  [AXE160224D-60P-LDH]  58.82 74.45 0 top
CN2  51536-01001-V01  [51536-01001-V01-10P-L]  18.43 22.68 90 bottom
CN3  SP09-13183-01 type-D  [HDMI-46765-1301-19P]  74.7 86.56 180 top
CN4  Micro SD  [CARD-CH1S-131-H-N-12P]  134.01 82.21 180 top
CN5  2M_13P2SF205_21pin  [FH35C-21S-0_3SHW-21P-LDH]  7.05 47.6 0 bottom
CN6  5M_13P2SF205_21pin  [FH35C-21S-0_3SHW-21P-LDH]  17.35 63.86 0 bottom
CN7  NG@NGFF  [MIPCI-APCI0026-P001A-75P-KB]  28.3 6.75 180 bottom
CN8  GS@ANT_JACK  [ANTENNA-20449-001E-4P]  44.22 18.7 0 bottom
CN9  FH35-31S-0.3SHW  [FH35C-31S-0_3SHW-31P-LDH]  52.85 37.09 180 bottom
CN10  BAT CONN  [50458-00801-001-8P-L]  119.47 45.86 270 bottom
CN11  TP CN  [FH34SRJ-6S-0_5SH-6P-L]  123.85 59.56 270 bottom
CN12  88266-040L  [88266-0400-4P-L]  130.12 69.37 180 bottom
CN13  50501-0120N-001  [88511-2001-20P-L]  143 71.16 180 bottom
CN14  ANT_JACK  [ANTENNA-20449-001E-4P]  167.99 68.71 0 bottom
CN15  ANT_JACK  [ANTENNA-20449-001E-4P]  156.11 67.51 90 bottom
CT1  emipad63x56  [EMIPAD63X56]  160.55 67.13 180 bottom
CT2  emipad63x56  [EMIPAD63X56]  173.71 71.36 190 bottom
D1  *RB500V-40  [DSM]  59.46 46.38 90 top
D2  *RB500V-40  [DSM]  61.62 46.38 90 top
D3  *14V/38V/100P_4  [CC0402_S]  65.81 82.32 0 top
D4  *5V/30V/0.2p_4  [CC0402_S]  81.43 78.26 270 top
D5  RB500V-40  [DSM]  90.57 80.8 0 top
D6  RB500V-40  [DSM]  90.57 76.99 0 top
D7  *5.5V/25V/410P_4  [CC0402_S]  102.51 77.75 90 top
D8  *5.5V/25V/410P_4  [CC0402_S]  104.8 77.75 270 top
D9  *RB751V40 40V/120mA  [DSMV]  113.81 81.81 90 bottom
F1  AP2331SA-7  [SOT23_213-3_3-2]  84.99 73.81 90 top
HE1  APX9132H  [SOT23_123-2_8-1_9]  104.39 82.12 270 top
HOLE1  *H-C71D71N  [H-C71D71N]  1.8 41.56 0 top
HOLE2  *H-C119D71P2  [H-C71D71N]  6.8 40.36 0 top
HOLE3  *O-EE6-1  [O-EE6-1]  5.8 80.86 0 top
HOLE4  *O-EE6-2  [O-EE6-2]  59.8 83.56 0 top
HOLE5  *O-EE6-3  [O-EE6-3]  97.8 83.46 0 top
HOLE6  *H-C236D79P2  [H-C236D79P2]  109.6 35.46 0 top
HOLE7  GS@EE6-SHIELDING-7  [EE6-SHIELDING-7]  26.54 13.57 180 bottom
HOLE8  -  [EE6-SHIELDING-8]  26.51 28.32 180 bottom
HOLE9  -  [EE6-SHIELDING-11]  23.59 46.88 180 bottom
HOLE10  -  [EE6-SHIELDING-10]  146.71 84.46 180 bottom
HOLE11  -  [EE6-SHIELDING-6]  88.49 33.86 0 top
HOLE12  *O-EE6-5  [O-EE6-5]  17.04 73.56 0 top
HOLE13  *H-C197D79P2  [H-C197D79P2]  173.32 67.08 0 top
J1  NG@SIM SOCKET  [SIMCARD-159-1000302603-10P-L]  113.96 81.16 180 top
L1  120Ohm@100MHz  [RC0402_S]  100.23 35.84 270 top
L2  NG@120ohm@100MHz  [CC0402_S]  112.29 69.24 270 top
L3  PBY160808T-250Y-N/3A/25ohm_6  [RC0603]  120.9 54.89 0 top
L4  *2.2uH_LQM21PN2R2NGC_0.8A  [RC0805_S]  163.09 75.82 180 top
L5  BLM15PD121SN1D  [RC0402_S]  18.82 81.43 180 bottom
L6  GS@6.8nH_4  [RC0402_S]  32.22 18.04 180 bottom
L7  GS@0_4  [RC0402_S]  33.93 20.47 270 bottom
L8  GS@BLM15AG601SN1D  [RC0402_S]  36.73 15.65 270 bottom
L9  GS@6.8nH_4  [RC0402_S]  38.46 20.85 270 bottom
L10  DLW21HN900SQ2L  [CHOKE-WCM2012-4P]  49.55 43.08 270 bottom
L11  DLW21HN900SQ2L  [CHOKE-WCM2012-4P]  51.33 43.08 270 bottom
L12  DLW21HN900SQ2L  [CHOKE-WCM2012-4P]  53.11 43.08 270 bottom
L13  DLW21HN900SQ2L  [CHOKE-WCM2012-4P]  54.89 43.08 270 bottom
L14  DLW21HN900SQ2L  [CHOKE-WCM2012-4P]  56.66 43.08 270 bottom
L15  *SHORT_4  [SHORT0402_S]  115.52 80.42 180 bottom
L16  BLM15PD121SN1D  [RC0402_S]  120.29 80.54 0 bottom
L17  *SHORT_4  [SHORT0402_S]  119.91 81.94 90 bottom
L18  *SHORT_4  [SHORT0402_S]  119.02 67.84 270 bottom
L19  *SHORT_4  [SHORT0402_S]  120.8 81.94 90 bottom
L20  *SHORT_4  [SHORT0402_S]  120.8 67.84 270 bottom
L21  0_4  [RC0402_S]  127.1 75.9 90 bottom
L22  0_4  [RC0402_S]  128.88 75.9 90 bottom
L23  0_4  [RC0402_S]  131.54 75.9 90 bottom
L24  0_4  [RC0402_S]  133.32 75.9 90 bottom
L25  *SHORT_4  [SHORT0402_S]  141.12 76.99 0 bottom
L26  *SHORT_4  [SHORT0402_S]  141.12 76.1 0 bottom
L27  2.2uH_LQM2MPN2R2NG0L_1.2A  [L2X1_6-1H]  150.77 82.37 180 bottom
L28  *6.8nH_4  [RC0402_S]  166.01 71.4 270 bottom
L29  *6.8nH_4  [RC0402_S]  152.42 68.4 0 bottom
L30  *6.8nH_4  [RC0402_S]  167.57 70.93 180 bottom
L31  *6.8nH_4  [RC0402_S]  153.82 67.93 90 bottom
LED1  DUAL_LIGHT  [LED12-22-BXY2P-C31-2C-3P]  3.35 72.48 90 top
LED2  19-113/T1D-CP2Q2HY/3T  [LEDLTW-C191DS5]  6.8 74.35 0 bottom
LED3  19-113/T1D-CP2Q2HY/3T  [LEDLTW-C191DS5]  7.07 62.36 90 top
NOREF  -  [#2]  23.59 19.86 0 top
NOREF#2  -  [#2]  -1.5 -35.53 0 top
NOREF#3  -  [#2]  242.13 -16.58 0 top
PAD1  NG@PS-25G  [EMIPAD98X79]  11.86 40.76 0 bottom
PAD2  NG@PS-25G  [EMIPAD98X79]  14.12 1.42 270 bottom
PC1  10U/25V/X5R_8  [CC0805]  77.72 57.68 0 top
PC2  10U/25V/X5R_8  [CC0805]  77.75 55.25 0 top
PC3  0.1U/25V_4  [CC0402_S]  80.77 62.71 90 top
PC4  1U/16V/X5R_4  [CC0402_S]  82.55 62.76 0 top
PC5  47P/50V/NPO_4  [CC0402_S]  81.18 61.24 0 top
PC6  10u/6.3V_6  [CC0603]  82.32 58.19 270 top
PC7  47P/50V/NPO_4  [CC0402_S]  82.7 64.92 90 top
PC8  100p/50V_4  [CC0402_S]  82.67 66.83 270 top
PC9  1U/16V/X5R_4  [CC0402_S]  82.83 54.89 0 top
PC10  0.1U/25V_4  [CC0402_S]  83.46 60.73 270 top
PC11  100p/50V_4  [CC0402_S]  83.59 64.92 270 top
PC12  2.2U/6.3V_4  [CC0402_S]  84.73 59.46 180 top
PC13  100p/50V_4  [CC0402_S]  84.6 64.92 270 top
PC14  1U/16V/X5R_4  [CC0402_S]  84.6 56.41 180 top
PC15  1U/16V/X5R_4  [CC0402_S]  84.6 54.89 0 top
PC16  1U/16V/X5R_4  [CC0402_S]  85.26 62.94 90 top
PC17  1U/16V/X5R_4  [CC0402_S]  86.38 54.89 0 top
PC18  0.1U/25V_4  [CC0402_S]  86.89 59.08 0 top
PC19  4.7u/10V_4  [CC0402_S]  87.78 65.3 180 top
PC20  0.1U/25V_4  [CC0402_S]  87.78 64.42 0 top
PC21  1U/16V/X5R_4  [CC0402_S]  87.78 63.53 0 top
PC22  1U/16V/X5R_4  [CC0402_S]  87.78 62.64 0 top
PC23  1U/16V/X5R_4  [CC0402_S]  88.16 54.89 0 top
PC24  1U/16V/X5R_4  [CC0402_S]  88.41 66.83 90 top
PC25  0.1U/25V_4  [CC0402_S]  89.56 63.91 90 top
PC26  1U/16V/X5R_4  [CC0402_S]  89.56 60.1 270 top
PC27  *1u/10V_4  [CC0402]  100.61 75.21 180 top
PC28  0.1uF/16V_4  [CC0402_S]  115.59 48.41 90 top
PC29  0.1uF/16V_4  [CC0402_S]  115.59 46.64 90 top
PC30  1uF/6.3V_4  [CC0402_S]  116.1 45.24 0 top
PC31  0.1uF/16V_4  [CC0402_S]  116.48 47.52 270 top
PC32  0.1uF/16V_4  [CC0402_S]  117.24 43.59 270 top
PC33  1uF/6.3V_4  [CC0402_S]  118.13 43.59 90 top
PC34  33nF/25V_4  [CC0402_S]  119.02 43.59 270 top
PC35  0.1U/25V_4  [CC0402_S]  121.82 48.16 90 top
PC36  10u/6.3V_4  [CC0402_S]  151.79 69.24 90 top
PC37  0.1u/25V_4  [CC0402]  148.74 78.49 90 top
PC38  0.1u/25V_4  [CC0402]  149.76 78.49 90 top
PC39  1u/10V_4  [CC0402]  151.91 73.81 90 top
PC40  1u/10V_4  [CC0402]  145.06 73.94 90 top
PC41  1U/16V/X5R_4  [CC0402_S]  15.26 52.1 270 bottom
PC42  10u/6.3V_4  [CC0402_S]  22.5 19.33 90 bottom
PC43  1U/16V/X5R_4  [CC0402_S]  21.36 53.37 90 bottom
PC44  10u/6.3V_4  [CC0402_S]  59.33 50.7 0 bottom
PC45  10u/6.3V_4  [CC0402_S]  64.92 59.59 270 bottom
PC46  10u/6.3V_4  [CC0402_S]  65.43 51.97 270 bottom
PC47  1U/6.3V_4  [CC0402_S]  65.88 53.49 180 bottom
PC48  *1U/6.3V_4  [CC0402_S]  65.94 49.3 90 bottom
PC49  10U/25V_8  [CC0805]  69.75 46.13 0 bottom
PC50  *10U/25V_8  [CC0805]  69.75 44.1 0 bottom
PC51  *10U/25V_8  [CC0805]  69.49 42.06 0 bottom
PC52  10U/25V_8  [CC0805]  69.49 40.03 0 bottom
PC53  1U/6.3V_4  [CC0402_S]  71.27 48.67 90 bottom
PC54  100U/4V/X5R_8  [CC0805]  73.81 65.05 180 bottom
PC55  100U/4V/X5R_8  [CC0805]  73.81 63.02 180 bottom
PC56  100U/4V/X5R_8  [CC0805]  73.81 53.49 180 bottom
PC57  100U/4V/X5R_8  [CC0805]  74.19 73.69 90 bottom
PC58  10U/25V_8  [CC0805]  75.59 48.16 90 bottom
PC59  10U/25V_8  [CC0805]  75.59 43.84 90 bottom
PC60  100U/4V/X5R_8  [CC0805]  76.22 73.69 90 bottom
PC61  4.7U/25V/X5R_8  [CC0805]  76.73 69.88 270 bottom
PC62  4.7U/25V/X5R_8  [CC0805]  76.73 66.45 90 bottom
PC63  4.7U/25V/X5R_8  [CC0805]  76.73 63.02 270 bottom
PC64  4.7U/25V/X5R_8  [CC0805]  76.73 59.59 270 bottom
PC65  4.7U/25V/X5R_8  [CC0805]  76.73 56.16 90 bottom
PC66  100U/4V/X5R_8  [CC0805]  76.73 52.73 270 bottom
PC67  10u/6.3V_6  [CC0603]  78.38 63.02 270 bottom
PC68  4.7U/25V/X5R_8  [CC0805]  79.52 70.89 0 bottom
PC69  4.7U/25V/X5R_8  [CC0805]  79.52 55.4 0 bottom
PC70  10U/25V/X5R_8  [CC0805]  79.52 49.43 0 bottom
PC71  1U/10V_4  [CC0402_S]  77.24 47.91 270 bottom
PC72  100U/4V/X5R_8  [CC0805]  81.3 52.6 270 bottom
PC73  1U/10V_4  [CC0402_S]  82.32 38.63 0 bottom
PC74  100p/50V_4  [CC0402]  79.4 46.76 0 bottom
PC75  4.7U/25V/X5R_8  [CC0805]  82.95 70.89 180 bottom
PC76  4.7U/25V/X5R_8  [CC0805]  82.95 55.4 180 bottom
PC77  10U/25V/X5R_8  [CC0805]  82.95 49.43 0 bottom
PC78  100U/4V/X5R_8  [CC0805]  83.33 73.81 90 bottom
PC79  4.7u/10V_6  [CC0603]  85.37 57.43 0 bottom
PC80  1U/10V_4  [CC0402_S]  85.62 41.81 90 bottom
PC81  4.7u/10V_4  [CC0402_S]  85.75 68.35 0 bottom
PC82  22u/4V_6  [CC0603]  86.13 53.11 180 bottom
PC83  22u/4V_6  [CC0603]  86.13 51.84 180 bottom
PC84  22u/4V_6  [CC0603]  86.13 50.57 180 bottom
PC85  4.7U/25V/X5R_8  [CC0805]  86.38 70.89 0 bottom
PC86  0.47u/25V_6  [CC0402_S]  87.4 41.81 270 bottom
PC87  4.7u/10V_6  [CC0603]  88.03 57.43 180 bottom
PC88  4.7u/10V_6  [CC0603]  88.8 68.86 180 bottom
PC89  47U/4V/X5R_8 H0.85  [CC0805]  89.43 51.97 180 bottom
PC90  47U/4V/X5R_8 H0.85  [CC0805]  89.43 49.81 180 bottom
PC91  47U/4V/X5R_8 H0.85  [CC0805]  89.43 47.65 180 bottom
PC92  10u/6.3V_6  [CC0603]  90.07 64.67 90 bottom
PC93  4.7u/10V_4  [CC0402_S]  90.07 60.86 90 bottom
PC94  47U/4V/X5R_8 H0.85  [CC0805]  90.29 73.94 90 bottom
PC95  47U/4V/X5R_8 H0.85  [CC0805]  90.95 54.89 90 bottom
PC96  4.7u/10V_6  [CC0603]  91.34 64.67 90 bottom
PC97  47U/4V/X5R_8 H0.85  [CC0805]  93.11 75.34 180 bottom
PC98  47U/4V/X5R_8 H0.85  [CC0805]  93.11 73.31 180 bottom
PC99  22u/4V_6  [CC0603]  93.37 58.19 0 bottom
PC100  22u/4V_6  [CC0603]  93.37 57.05 0 bottom
PC101  22u/4V_6  [CC0603]  93.37 55.91 0 bottom
PC102  22u/4V_6  [CC0603]  93.37 53.37 180 bottom
PC103  22u/4V_6  [CC0603]  93.37 52.1 180 bottom
PC104  4.7u/10V_4  [CC0402_S]  93.62 71.65 0 bottom
PC105  10U/25V/X5R_8  [CC0805]  96.54 74.96 180 bottom
PC106  10u/25V/X5R_8  [CC0805]  96.54 72.92 180 bottom
PC107  10U/25V/X5R_8  [CC0805]  96.54 70.77 180 bottom
PC108  10U/25V/X5R_8  [CC0805]  96.54 68.73 180 bottom
PC109  10U/25V/X5R_8  [CC0805]  96.54 66.7 180 bottom
PC110  10U/25V/X5R_8  [CC0805]  96.54 77.12 180 bottom
PC111  22u/6.3V_6  [CC0603]  96.67 59.21 0 bottom
PC112  22u/6.3V_6  [CC0603]  96.67 57.94 0 bottom
PC113  22u/6.3V_6  [CC0603]  96.67 56.67 0 bottom
PC114  22u/6.3V_6  [CC0603]  96.67 55.4 0 bottom
PC115  22u/6.3V_6  [CC0603]  96.67 54.13 0 bottom
PC116  22u/6.3V_6  [CC0603]  96.67 52.86 0 bottom
PC117  22u/6.3V_6  [CC0603]  96.67 51.59 0 bottom
PC118  10u/25V_8  [CC0805]  99.74 57.08 180 bottom
PC119  4.7u/10V_6  [CC0402_S]  99.72 55.4 0 bottom
PC120  10u/6.3V_4  [CC0402_S]  99.92 61.49 0 bottom
PC121  0.047u/25V_4  [CC0402_S]  100.1 54 90 bottom
PC122  *150U/6.3V_3528  [CC3528]  101.62 75.59 0 bottom
PC123  1u/25V_4  [CC0402_S]  100.63 58.68 0 bottom
PC124  0.1U/10V_4  [CC0402_S]  103.4 66.19 180 bottom
PC125  0.1u/10V_4  [CC0402_S]  105.81 73.43 0 bottom
PC126  10u/6.3V_4  [CC0402_S]  106.32 46.64 90 bottom
PC127  22u/6.3V_6  [CC0603]  106.58 74.83 0 bottom
PC128  1U/6.3V_4  [CC0402_S]  106.83 61.24 180 bottom
PC129  22u/6.3V_6  [CC0603]  106.32 67.84 0 bottom
PC130  22u/6.3V_6  [CC0603]  106.32 66.19 0 bottom
PC131  10u/6.3V_4  [CC0402_S]  107.21 46.64 90 bottom
PC132  10u/6.3V_4  [CC0402_S]  107.85 52.99 180 bottom
PC133  *1U/6.3V_4  [CC0402_S]  109.75 75.34 180 bottom
PC134  *47P/50V_4  [CC0402_S]  108.86 68.61 0 bottom
PC135  0.1U/10V_4  [CC0402_S]  110.13 70.51 0 bottom
PC136  22uF/10V_1206  [CC1206]  144.42 81.94 90 bottom
PC137  10u/6.3V_4  [CC0402_S]  97.43 50.32 90 top
PD1  *CPDQR5V0-HF  [RC0402_S]  151.28 76.35 90 top
PD2  DFLS240-7-F  [D-2_8X1_78]  70.51 37.75 0 bottom
PD3  DFLS240-7-F  [D-2_8X1_78]  72.92 42.95 90 bottom
PD4  ZD6.2V  [D-0_9X0_6]  93.01 67.9 90 bottom
PL1  0.47uH_0806  [L2X1_6-1_6-1H]  74.06 69.88 180 bottom
PL2  1uH_0806  [L2X1_6-1_6-1H]  74.06 67.34 180 bottom
PL3  1uH_0806  [L2X1_6-1_6-1H]  74.06 60.73 0 bottom
PL4  0.47uH_0806  [L2X1_6-1_6-1H]  74.06 58.32 0 bottom
PL5  0.47uH_0806  [L2X1_6-1_6-1H]  74.06 55.78 0 bottom
PL6  10uH/1.3A_5X5X1.8  [CHOKE-1124BS-3R3M]  77.11 38.89 270 bottom
PL7  0.47uH_0806  [L2X1_6-1_6-1H]  78.51 73.56 90 bottom
PL8  0.47uH_0806  [L2X1_6-1_6-1H]  79.02 52.86 90 bottom
PL9  0.47uH_0806  [L2X1_6-1_6-1H]  81.05 73.56 90 bottom
PL10  0.47uH_0806  [L2X1_6-1_6-1H]  83.59 52.86 90 bottom
PL11  0.47uH_0806  [L2X1_6-1_6-1H]  85.62 73.56 90 bottom
PL12  1uH_0806  [L2X1_6-1_6-1H]  86 55.27 270 bottom
PL13  1uH_0806  [L2X1_6-1_6-1H]  88.03 73.56 270 bottom
PL14  0.47uH_0806  [L2X1_6-1_6-1H]  88.67 55.27 270 bottom
PL15  0.47uH_0806  [L2X1_6-1_6-1H]  89.68 70.77 180 bottom
PL16  1uH_0806  [L2X1_6-1_6-1H]  92.99 69.88 0 bottom
PL17  0.47uH_0806  [L2X1_6-1_6-1H]  93.24 64.54 270 bottom
PL18  0.47uH_0806  [L2X1_6-1_6-1H]  93.24 60.48 90 bottom
PL19  2.2uH/5A_5X5X1.8  [CHOKE-MMD-05AH-4R7M-X2Q]  101.62 70.51 90 bottom
PL20  2.2uH/5A_5X5X1.8  [CHOKE-MMD-05AH-4R7M-X2Q]  102.38 49.05 0 bottom
PL21  BLM18PG221SN1D  [RC0603]  144.29 78.26 0 bottom
PL22  BLM18PG221SN1D  [RC0603]  144.29 76.73 0 bottom
PQ2  AO3415  [SOT23_213-3_3-2]  126.26 68.61 270 top
PQ3  BSN20  [SOT23_213-3_3-2]  145.31 70.77 270 top
PQ4  AON7407  [PG-TSDSON-8-8P-R]  149.25 70.64 90 top
PQ5  BSN20  [SOT23_213-3_3-2]  23.39 28.47 90 bottom
PQ6  AON7407  [PG-TSDSON-8-8P-R]  23.52 23.27 90 bottom
PQ7  *TPCC8067  [POWER-3_3X3_3-65-5P-SMT]  62.38 50.19 90 bottom
PQ8  TPCC8067  [POWER-3_3X3_3-65-5P-SMT]  64.79 56.41 0 bottom
PQ9  TPCC8067  [POWER-3_3X3_3-65-5P-SMT]  68.98 50.06 0 bottom
PQ10  AON7407  [PG-TSDSON-8-8P-R]  78.76 43.84 90 bottom
PQ11  AON7407  [PG-TSDSON-8-8P-R]  103.15 62.51 0 bottom
PQ12  AON7407  [PG-TSDSON-8-8P-R]  95.02 51.33 90 top
PQ13  BSN20  [SOT23_213-3_3-2]  94.51 56.29 90 top
PR1  *Short_8  [SHORT0805]  78.13 63.27 180 top
PR2  *Short_4  [SHORT0402_S]  78.76 61.62 180 top
PR3  *Short_4  [SHORT0402_S]  80.92 58.17 90 top
PR4  *Short_4  [SHORT0402_S]  82.57 60.73 90 top
PR6  *10K_4  [RC0402_S]  84.1 67.21 180 top
PR7  47K_4  [RC0402_S]  84.1 66.32 0 top
PR8  *Short_4  [SHORT0402_S]  85.54 67.41 90 top
PR12  *Short_6  [SHORT0603]  87.02 67.34 90 top
PR14  *Short_4  [SHORT0402_S]  87.78 60.73 180 top
PR16  *Short_4  [SHORT0402_S]  89.3 57.56 90 top
PR17  *Short_4  [SHORT0402_S]  89.68 67.34 180 top
PR18  *0_4  [RC0402_S]  89.68 66.45 0 top
PR19  *0_4  [RC0402_S]  90.19 57.56 270 top
PR20  *Short_4  [SHORT0402_S]  91.08 63.53 0 top
PR22  *Short_4  [SHORT0402_S]  106.45 55.07 180 top
PR23  100/F_4  [RC0402_S]  114.58 48.29 270 top
PR24  100/F_4  [RC0402_S]  114.58 46.51 90 top
PR25  *Short_4  [SHORT0402_S]  114.32 45.24 180 top
PR26  *Short_4  [SHORT0402_S]  114.58 43.59 270 top
PR27  100K/F_4  [RC0402_S]  115.47 43.59 90 top
PR28  *Short_4  [SHORT0402_S]  116.35 43.59 270 top
PR29  *Short_4  [SHORT0402_S]  117.5 49.94 90 top
PR30  100K/F_4  [RC0402_S]  118.39 49.94 270 top
PR31  *Short_4  [SHORT0402_S]  120.29 51.46 90 top
PR32  1.8M/F_4  [RC0402_S]  119.91 43.59 90 top
PR33  *Short_4  [SHORT0402_S]  121.18 51.46 90 top
PR34  *10K_4  [RC0402_S]  120.8 43.59 90 top
PR35  1K/F_4  [RC0402_S]  121.82 46.38 90 top
PR36  18.2K/F_4  [RC0402_S]  121.69 44.6 270 top
PR37  *Short_4  [SHORT0402_S]  121.82 42.83 270 top
PR38  *100K/F_4  [RC0402_S]  142.9 70.13 90 top
PR39  100K/F_4  [RC0402_S]  148.49 73.43 180 top
PR41  10/F_4  [RC0402_S]  148.99 76.35 90 top
PR42  10/F_4  [RC0402_S]  150.01 76.35 90 top
PR43  *18K/F_4  [RC0402_S]  163.6 73.53 180 top
PR44  10K/F_4  [RC0402_S]  18.31 48.67 90 bottom
PR45  *0_4  [RC0402_S]  19.2 48.67 270 bottom
PR47  *100K/F_4  [RC0402_S]  23.01 30.89 0 bottom
PR49  100K/F_4  [RC0402_S]  23.64 26.06 0 bottom
PR50  22_4  [RC0402_S]  51.84 76.23 90 bottom
PR51  22_4  [RC0402_S]  52.73 76.23 90 bottom
PR52  22_4  [RC0402_S]  53.62 76.23 90 bottom
PR53  *0_4  [RC0402_S]  57.93 50.57 90 bottom
PR54  24.9K/F_4  [RC0402_S]  84.2 68.73 90 top
PR55  47K/F_4  [RC0402_S]  135.53 78.74 180 bottom
PR57  10K_4  [RC0402_S]  64.92 66.83 90 bottom
PR58  *Short_4  [SHORT0402_S]  65.81 59.59 270 bottom
PR59  *Short_4  [SHORT0402_S]  66.06 73.43 90 bottom
PR60  *Short_4  [SHORT0402_S]  66.32 51.97 270 bottom
PR61  10K_4  [RC0402_S]  66.95 66.83 90 bottom
PR63  71.5/F_4  [RC0402_S]  73.94 61.24 0 top
PR64  71.5/F_4  [RC0402_S]  73.94 59.46 0 top
PR65  71.5/F_4  [RC0402_S]  73.94 60.35 0 top
PR66  *Short_4  [SHORT0402_S]  67.59 56.54 0 bottom
PR67  *Short_4  [SHORT0402_S]  69.36 64.54 180 bottom
PR68  *Short_4  [SHORT0402_S]  69.36 63.65 180 bottom
PR69  *Short_4  [SHORT0402_S]  69.36 62.76 0 bottom
PR70  *Short_4  [SHORT0402_S]  69.36 56.54 0 bottom
PR71  *Short_4  [SHORT0402_S]  67.59 55.58 0 bottom
PR74  *0_4  [RC0402_S]  71.14 64.54 0 bottom
PR75  *0_4  [RC0402_S]  71.14 63.65 0 bottom
PR76  *0_4  [RC0402_S]  71.14 62.76 0 bottom
PR77  *Short_4  [SHORT0402_S]  71.78 50.7 0 bottom
PR79  *Short_6  [SHORT0603]  73.81 48.54 90 bottom
PR80  *Short_4  [SHORT0402_S]  78.25 77.88 180 bottom
PR81  100/F_4  [RC0402_S]  78.25 76.99 0 bottom
PR83  71.5/F_4  [RC0402_S]  79.65 77.5 90 bottom
PR84  71.5/F_4  [RC0402_S]  80.67 77.5 90 bottom
PR85  *Short_4  [SHORT0402_S]  81.56 77.5 270 bottom
PR86  1M/F_4  [RC0402_S]  82.32 39.52 0 bottom
PR87  249K/F_4  [RC0402_S]  84.1 35.59 180 bottom
PR88  301K/F_4  [RC0402_S]  82.32 40.41 180 bottom
PR89  *Short_4  [SHORT0402_S]  82.45 77.5 270 bottom
PR91  20K/F_4  [RC0402_S]  85.87 35.59 180 bottom
PR92  *Short_4  [SHORT0402_S]  83.23 77.5 90 bottom
PR93  *Short_4  [SHORT0402_S]  84.2 77.5 270 bottom
PR94  *0_4  [RC0402_S]  84.73 41.81 270 bottom
PR95  *Short_4  [SHORT0402_S]  85.19 77.5 90 bottom
PR96  20K/F_4  [RC0402_S]  86 77.5 270 bottom
PR99  51K/F_4  [RC0402_S]  86.51 41.81 90 bottom
PR100  *Short_4  [SHORT0402_S]  87.27 43.59 0 bottom
PR107  24.9K/F_4  [RC0402_S]  83.21 68.73 90 top
PR108  47K/F_4  [RC0402_S]  63.4 72.52 0 bottom
PR109  2.21K/F_4  [RC0402_S]  97.99 63.32 180 bottom
PR110  2.21K/F_4  [RC0402_S]  97.99 62.43 180 bottom
PR111  2.21K/F_4  [RC0402_S]  97.99 61.6 180 bottom
PR112  2.21K/F_4  [RC0402_S]  98.02 60.68 180 bottom
PR114  24.9K/F_4  [RC0402_S]  82.37 68.73 90 top
PR115  47K/F_4  [RC0402_S]  89.81 44.02 270 bottom
PR116  10K/F_4  [RC0402_S]  104.42 59.59 90 bottom
PR117  *Short_4  [SHORT0402_S]  105.43 59.59 90 bottom
PR118  *Short_4  [SHORT0402_S]  106.45 59.59 90 bottom
PR119  *Short_6  [SHORT0603]  106.32 77.12 180 bottom
PR120  *Short_6  [SHORT0603]  107.08 63.53 0 bottom
PR122  *Short_4  [SHORT0402_S]  107.46 59.59 90 bottom
PR123  *100K_4  [RC0402_S]  108.1 58.32 180 bottom
PR124  10K/F_4  [RC0402_S]  108.1 57.43 0 bottom
PR125  *100K_4  [RC0402_S]  108.1 56.54 180 bottom
PR126  191/F_4  [RC0402_S]  108.1 55.65 0 bottom
PR127  41.2K/F_4  [RC0402_S]  108.1 54.76 180 bottom
PR128  41.2K/F_4  [RC0402_S]  108.1 53.87 180 bottom
PR129  10K/F_4  [RC0402_S]  108.48 59.59 90 bottom
PR130  10m/F_612  [RC3216]  108.99 43.89 270 bottom
PR132  178K/F_4  [RC0402_S]  108.48 66.32 270 bottom
PR133  100K/F_4  [RC0402_S]  109.75 77.12 180 bottom
PR134  *100K/F_4  [RC0402_S]  109.75 76.23 0 bottom
PR135  100K/F_4  [RC0402_S]  110 71.78 90 bottom
PR136  1M/F_4  [RC0402_S]  108.86 67.72 180 bottom
PR137  *Short_4  [SHORT0402_S]  109.88 58.32 0 bottom
PR138  *Short_4  [SHORT0402_S]  109.88 57.43 0 bottom
PR139  10K/F_4  [RC0402_S]  109.88 56.54 0 bottom
PR140  24.9K/F_4  [RC0402_S]  109.88 55.65 0 bottom
PR141  24.9K/F_4  [RC0402_S]  109.88 54.76 0 bottom
PR142  100/F_4  [RC0402_S]  110.13 69.62 180 bottom
PR143  *SHORT_4  [SHORT0402]  106.83 64.67 180 bottom
PR144  *100K/F_4  [RC0402_S]  110.39 73.56 270 bottom
PR145  *0_4  [RC0402_S]  97.3 60.99 270 top
PR146  100K/F_4  [RC0402_S]  96.42 60.99 270 top
PR147  100K/F_4  [RC0402_S]  95.53 60.99 90 top
PR148  *Short_4  [SHORT0402_S]  98.19 60.99 90 top
PR149  *Short_4  [SHORT0402_S]  89.3 68.23 0 top
PR150  *Short_4  [SHORT0402_S]  89.56 65.3 0 top
PR151  *0_6  [RC0603]  97.69 52.6 90 top
PR152  100K/F_4  [RC0402_S]  94.76 54.13 180 top
PR153  10K_4  [RC0402_S]  97.43 57.56 0 top
PR666  *Short_6  [SHORT0603]  67.97 58.95 180 bottom
PU1  bq27520YZFR-G4  [BGA15-TEXAS-BQ27520YZFT-G3]  118.89 46.76 0 top
PU2  G9090-280T11U  [SOT23-5-2_8-95-5P-1_3H]  18.31 51.59 0 bottom
PU3  G546B1RD1U  [TDFN8-3X3-65-9P]  65.94 70 0 bottom
PU4  G708  [SOT23-5]  84.22 44.48 0 bottom
PU5  BD2610GW  [BGA224-ROHM-BD2610GW-E2-0_5S]  84.48 63.15 90 bottom
PU6  TPS61176  [QFN16-3X3-5-17P-TPS61176RTE]  86 38.38 0 bottom
PU7  BQ24190  [QFN24-4X4-5-34P]  104.29 54.89 270 bottom
PU8  TPS63000  [QFN10-3X3-5-11P]  106.83 71.02 90 bottom
Q1  NG@PJ4N3KDW  [SC70-2_1-65-6P]  36.6 11.96 0 top
Q2  2SK3541  [VMT3-1_2-8]  58.82 38.89 0 top
Q3  2SK3541  [VMT3-1_2-8]  58.7 36.73 0 top
Q4  2SK3541  [VMT3-1_2-8]  68.98 78 90 top
Q5  *2SK3541  [VMT3-1_2-8]  70.63 53.75 180 top
Q6  2SK3541  [VMT3-1_2-8]  80.16 75.34 0 top
Q7  AO3402  [SOT23_213-3_3-2]  84.99 81.81 0 top
Q8  AO3402  [SOT23_213-3_3-2]  84.99 77.88 0 top
Q9  PJ4N3KDW  [SC70-2_1-65-6P]  85.11 46.76 90 top
Q10  PJ4N3KDW  [SC70-2_1-65-6P]  102 43.46 90 top
Q11  PJ4N3KDW  [SC70-2_1-65-6P]  125.75 62.26 270 top
Q12  2SK3541  [VMT3-1_2-8]  7.39 67.34 90 top
Q13  2SK3541  [VMT3-1_2-8]  8.91 74.07 270 bottom
Q14  PJ4N3KDW  [SC70-2_1-65-6P]  16.28 43.97 270 bottom
Q15  2SK3541  [VMT3-1_2-8]  19.71 42.32 0 bottom
Q16  *2SK3541  [VMT3-1_2-8]  20.47 47.4 270 bottom
Q17  2SK3541  [VMT3-1_2-8]  91.97 43.46 90 bottom
Q18  PJ4N3KDW  [SC70-2_1-65-6P]  72.39 50.65 0 top
Q22  AO3413  [SOT23_213-3_3-2]  53.24 41.05 180 top
Q23  2SK3541  [VMT3-1_2-8]  49.17 40.67 270 top
Q24  PJ4N3KDW  [SC70-2_1-65-6P]  85.62 42.32 180 top
R1  *SHORT_4  [SHORT0402_S]  2.56 49.05 180 top
R2  *SHORT_4  [SHORT0402_S]  2.56 46 270 top
R3  10K/F_4  [RC0402_S]  2.56 44.27 270 top
R4  150/J_4  [RC0402_S]  6.25 71.15 180 top
R6  100/J_4  [RC0402_S]  6.25 72.04 180 top
R7  *SHORT_4  [SHORT0402_S]  7.52 48.92 0 top
R8  *SHORT_4  [SHORT0402_S]  12.21 44.35 0 bottom
R9  0_4  [RC0402_S]  12.21 43.46 0 bottom
R10  300/F_4  [RC0402_S]  33.02 57.63 180 top
R11  300/F_4  [RC0402_S]  33.07 71.07 0 top
R12  300/F_4  [RC0402_S]  33.14 74.6 180 top
R13  300/F_4  [RC0402_S]  33.4 56.62 180 top
R14  *10K_4  [RC0402_S]  33.42 34.82 90 top
R15  *10K_4  [RC0402_S]  34.31 34.82 90 top
R16  *SHORT_4  [SHORT0402_S]  38.38 38.51 270 top
R17  *SHORT_4  [SHORT0402_S]  39.27 50.83 90 top
R18  NG@100K_4  [RC0402_S]  39.65 11.96 180 top
